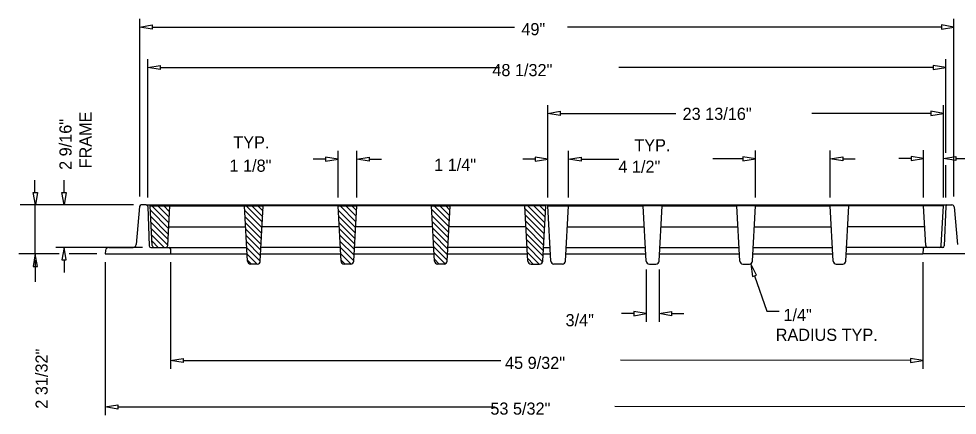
# Model space of a CAD drawing. Extents: x 12.38 to 19.62, y 5.98 to 15.83.
# Drawn here: x 12.375 to 17.009, y 10.382 to 12.339 of the extents above; entities that cross this region are included whole.
import ezdxf

# ---------------------------------------------------------------- set-up
doc = ezdxf.new("R2010")
doc.units = 0
for name, color, linetype in [('Default', 7, 'Continuous'), ('DIMS', 7, 'Continuous'), ('FRAME', 7, 'Continuous'), ('HATCH', 7, 'Continuous'), ('TOP', 7, 'Continuous'), ('V7_LEVEL_12', 7, 'Continuous')]:
    doc.layers.add(name, color=color, linetype=linetype)

# ---------------------------------------------------------------- blocks, each defined once
blk = doc.blocks.new('_X36')
at = {"layer": 'Default'}
for p, q in [((705.4, 291.74), (705.46, 291.81)), ((705.58, 288.39), (709, 291.81)), ((705.76, 285.03), (712.53, 291.81)), ((705.94, 281.68), (716.07, 291.81)), ((706.12, 278.32), (717.8, 290)), ((706.3, 274.97), (717.6, 286.26)), ((706.48, 271.61), (717.39, 282.52)), ((706.66, 268.26), (717.19, 278.79)), ((706.85, 264.9), (716.99, 275.05)), ((707.03, 261.55), (716.79, 271.31)), ((707.24, 258.23), (716.59, 267.58)), ((709.35, 256.81), (716.39, 263.84)), ((712.89, 256.81), (716.19, 260.1))]:
    blk.add_line(p, q, dxfattribs=at)
blk = doc.blocks.new('_X35')
at = {"layer": 'Default'}
for p, q in [((763.03, 289.27), (765.57, 291.81)), ((763.21, 285.92), (769.1, 291.81)), ((763.39, 282.56), (772.64, 291.81)), ((763.57, 279.21), (774.03, 289.66)), ((763.76, 275.85), (773.83, 285.92)), ((763.94, 272.5), (773.63, 282.19)), ((764.12, 269.14), (773.42, 278.45)), ((764.3, 265.79), (773.22, 274.71)), ((764.48, 262.43), (773.02, 270.98)), ((764.66, 259.08), (772.82, 267.24)), ((766.01, 256.89), (772.62, 263.5)), ((769.46, 256.81), (772.42, 259.76))]:
    blk.add_line(p, q, dxfattribs=at)
blk = doc.blocks.new('_X34')
at = {"layer": 'Default'}
for p, q in [((819.3, 288.97), (822.14, 291.81)), ((819.48, 285.61), (825.67, 291.81)), ((819.66, 282.26), (829.21, 291.81)), ((819.84, 278.9), (830.26, 289.32)), ((820.02, 275.55), (830.06, 285.59)), ((820.2, 272.19), (829.86, 281.85)), ((820.38, 268.84), (829.66, 278.11)), ((820.56, 265.49), (829.46, 274.38)), ((820.75, 262.13), (829.25, 270.64)), ((820.93, 258.78), (829.05, 266.9)), ((822.51, 256.83), (828.85, 263.17)), ((826.03, 256.81), (828.65, 259.43))]:
    blk.add_line(p, q, dxfattribs=at)
blk = doc.blocks.new('_X33')
at = {"layer": 'Default'}
for p, q in [((875.56, 288.67), (878.7, 291.81)), ((875.75, 285.31), (882.24, 291.81)), ((875.93, 281.96), (885.77, 291.81)), ((876.11, 278.6), (886.49, 288.99)), ((876.29, 275.25), (886.29, 285.25)), ((876.47, 271.89), (886.09, 281.51)), ((876.65, 268.54), (885.89, 277.78)), ((876.83, 265.18), (885.69, 274.04)), ((877.01, 261.83), (885.49, 270.3)), ((877.2, 258.48), (885.28, 266.57)), ((879.06, 256.81), (885.08, 262.83)), ((882.59, 256.81), (884.88, 259.09))]:
    blk.add_line(p, q, dxfattribs=at)
blk = doc.blocks.new('_X37')
at = {"layer": 'Default'}
for p, q in [((544.01, 208.13), (544.18, 208.3)), ((544.19, 204.78), (547.71, 208.3)), ((544.37, 201.42), (551.25, 208.3)), ((544.55, 198.07), (554.78, 208.3)), ((544.73, 194.71), (555.74, 205.72)), ((544.91, 191.36), (555.53, 201.98)), ((545.09, 188.01), (555.33, 198.24)), ((545.27, 184.65), (555.13, 194.51)), ((547.46, 183.3), (554.93, 190.77)), ((551, 183.3), (554.73, 187.03))]:
    blk.add_line(p, q, dxfattribs=at)

msp = doc.modelspace()

# ---------------------------------------------------------------- linework, layer by layer
at = {"layer": 'DIMS'}
for p, q in [((12.9725, 11.4612), (12.9725, 12.3391)), ((16.992, 11.4612), (16.992, 12.3391)), ((13.034, 12.2981), (14.8232, 12.2981)), ((16.9305, 12.2981), (15.0849, 12.2981)), ((13.0125, 11.4564), (13.0125, 12.1399)), ((16.9515, 11.6781), (16.9515, 12.1399)), ((13.074, 12.0988), (14.7493, 12.0988)), ((16.8899, 12.0988), (15.3383, 12.0988)), ((14.9873, 11.4564), (14.9873, 11.9133)), ((16.9402, 11.4564), (16.9402, 11.9133)), ((15.0488, 11.8723), (15.6199, 11.8723)), ((16.8787, 11.8723), (16.2908, 11.8723)), ((13.9516, 11.4564), (13.9516, 11.6867)), ((14.0439, 11.4564), (14.0439, 11.6867)), ((15.0896, 11.4564), (15.0896, 11.687)), ((16.0124, 11.4564), (16.0124, 11.6888)), ((16.3815, 11.4564), (16.3815, 11.6888)), ((16.8428, 11.4564), (16.8428, 11.6903)), ((13.8901, 11.6457), (13.8286, 11.6457)), ((14.1054, 11.6457), (14.1669, 11.6457)), ((14.9256, 11.646), (14.8641, 11.646)), ((15.1511, 11.646), (15.3383, 11.646)), ((15.9508, 11.6478), (15.8017, 11.6478)), ((16.443, 11.6478), (16.5045, 11.6478)), ((16.7813, 11.6493), (16.7198, 11.6493)), ((17.0017, 11.6493), (17.0632, 11.6493)), ((16.9515, 11.4564), (16.9515, 11.6165)), ((12.4552, 11.4817), (12.4552, 11.5432)), ((12.5987, 11.4817), (12.5987, 11.5432)), ((12.9411, 11.4202), (12.3824, 11.4202)), ((12.5754, 11.178), (12.3753, 11.178)), ((12.9859, 11.2103), (12.5577, 11.2103)), ((12.7613, 11.178), (12.6234, 11.178)), ((12.4563, 11.1472), (12.4563, 11.0398)), ((12.5987, 11.1488), (12.5987, 11.0873)), ((12.8023, 11.1383), (12.8023, 10.3821)), ((13.125, 11.1383), (13.125, 10.6114)), ((16.8389, 11.1383), (16.8389, 10.6114)), ((15.4734, 11.1019), (15.4734, 10.8425)), ((15.5363, 11.1019), (15.5363, 10.8425)), ((16.0075, 11.0706), (16.0685, 10.8963)), ((16.0685, 10.8963), (16.13, 10.8963)), ((15.4119, 10.8835), (15.3504, 10.8835)), ((15.5978, 10.8835), (15.6593, 10.8835)), ((13.1865, 10.6524), (14.755, 10.6524)), ((16.7774, 10.6524), (15.3465, 10.654)), ((12.8638, 10.4231), (14.7265, 10.4231)), ((17.1002, 10.4231), (15.3179, 10.4245))]:
    msp.add_line(p, q, dxfattribs=at)
for points in [[(13.034, 12.3084), (13.034, 12.2879), (12.9725, 12.2981)], [(16.9305, 12.3084), (16.9305, 12.2879), (16.992, 12.2981)], [(13.074, 12.1091), (13.074, 12.0886), (13.0125, 12.0988)], [(16.8899, 12.1091), (16.8899, 12.0886), (16.9515, 12.0988)], [(15.0488, 11.8825), (15.0488, 11.862), (14.9873, 11.8723)], [(16.8787, 11.8825), (16.8787, 11.862), (16.9402, 11.8723)], [(13.8901, 11.6559), (13.8901, 11.6354), (13.9516, 11.6457)], [(14.1054, 11.6559), (14.1054, 11.6354), (14.0439, 11.6457)], [(14.9256, 11.6562), (14.9256, 11.6357), (14.9871, 11.646)], [(15.1511, 11.6562), (15.1511, 11.6357), (15.0896, 11.646)], [(15.9508, 11.6581), (15.9508, 11.6376), (16.0124, 11.6478)], [(16.443, 11.6581), (16.443, 11.6376), (16.3815, 11.6478)], [(16.7813, 11.6596), (16.7813, 11.6391), (16.8428, 11.6493)], [(17.0017, 11.6596), (17.0017, 11.6391), (16.9402, 11.6493)], [(12.4469, 11.4817), (12.4674, 11.4817), (12.4572, 11.4202)], [(12.5885, 11.4817), (12.609, 11.4817), (12.5987, 11.4202)], [(12.4467, 11.1165), (12.4672, 11.1165), (12.457, 11.178)], [(12.5885, 11.1488), (12.609, 11.1488), (12.5987, 11.2103)], [(15.9977, 11.0676), (16.0173, 11.0736), (15.9893, 11.1294)], [(15.4119, 10.8938), (15.4119, 10.8733), (15.4734, 10.8835)], [(15.5978, 10.8938), (15.5978, 10.8733), (15.5363, 10.8835)], [(13.1865, 10.6627), (13.1865, 10.6422), (13.125, 10.6524)], [(16.7774, 10.6627), (16.7774, 10.6422), (16.8389, 10.6524)], [(12.8638, 10.4333), (12.8638, 10.4128), (12.8023, 10.4231)]]:
    msp.add_lwpolyline(points, close=True, dxfattribs=at)
at = {"layer": 'FRAME'}
for p, q in [((12.9718, 11.4132), (12.9553, 11.2244)), ((13.0047, 11.4202), (12.9795, 11.4202)), ((13.0047, 11.4202), (16.9579, 11.4202)), ((13.0124, 11.4128), (13.0192, 11.2177)), ((16.9515, 11.4128), (16.9447, 11.2177)), ((16.9592, 11.4202), (16.9826, 11.4202)), ((16.9928, 11.4109), (17.0091, 11.2244)), ((12.8032, 11.195), (12.8023, 11.178)), ((12.8023, 11.178), (13.125, 11.178)), ((12.8193, 11.2103), (12.94, 11.2103)), ((13.0269, 11.2103), (13.1172, 11.2103)), ((13.1236, 11.2042), (13.125, 11.178)), ((13.125, 11.178), (13.503, 11.178)), ((13.5697, 11.178), (13.9644, 11.178)), ((14.0311, 11.178), (14.4258, 11.178)), ((14.4924, 11.178), (14.8871, 11.178)), ((14.964, 11.178), (14.9999, 11.178)), ((14.9658, 11.2103), (14.9982, 11.2103)), ((15.0768, 11.178), (15.4715, 11.178)), ((15.5382, 11.178), (15.9329, 11.178)), ((15.9996, 11.178), (16.3943, 11.178)), ((16.4609, 11.178), (16.8389, 11.178)), ((16.8403, 11.2042), (16.8389, 11.178)), ((17.1617, 11.178), (16.8389, 11.178)), ((16.937, 11.2103), (16.8468, 11.2103))]:
    msp.add_line(p, q, dxfattribs=at)
for centre, radius, start, end in [((12.9795, 11.4125), 0.00769, 90, 175), ((13.0047, 11.4125), 0.00769, 2, 90), ((16.9592, 11.4125), 0.00769, 90, 178), ((16.9826, 11.41), 0.0103, 5, 90), ((12.94, 11.2257), 0.0154, 270, 355), ((13.0269, 11.218), 0.00769, 182, 270), ((16.937, 11.218), 0.00769, 270, 358), ((12.8193, 11.1942), 0.0161, 90, 177), ((13.1172, 11.2038), 0.00648, 3, 90), ((16.8468, 11.2038), 0.00648, 90, 177)]:
    msp.add_arc(centre, radius, start, end, dxfattribs=at)
at = {"layer": 'TOP'}
for p, q in [((13.0343, 11.22), (13.0237, 11.4154)), ((13.0237, 11.4154), (13.1211, 11.4154)), ((13.1106, 11.22), (13.1211, 11.4154)), ((13.1211, 11.4154), (13.4902, 11.4154)), ((13.5049, 11.143), (13.4902, 11.4154)), ((13.4902, 11.4154), (13.5825, 11.4154)), ((13.5678, 11.143), (13.5825, 11.4154)), ((13.9516, 11.4154), (13.5825, 11.4154)), ((13.9663, 11.143), (13.9516, 11.4154)), ((13.9516, 11.4154), (14.0439, 11.4154)), ((14.0292, 11.143), (14.0439, 11.4154)), ((14.413, 11.4154), (14.0439, 11.4154)), ((14.413, 11.4154), (14.5052, 11.4154)), ((14.4276, 11.143), (14.413, 11.4154)), ((14.4905, 11.143), (14.5052, 11.4154)), ((14.8743, 11.4154), (14.5052, 11.4154)), ((14.9768, 11.4154), (14.8743, 11.4154)), ((14.889, 11.1429), (14.8743, 11.4154)), ((14.9621, 11.1429), (14.9768, 11.4154)), ((14.9871, 11.4154), (15.0896, 11.4154)), ((15.0018, 11.1429), (14.9871, 11.4154)), ((15.0749, 11.1429), (15.0896, 11.4154)), ((15.0896, 11.4154), (15.4587, 11.4154)), ((15.4734, 11.143), (15.4587, 11.4154)), ((15.551, 11.4154), (15.4587, 11.4154)), ((15.5363, 11.143), (15.551, 11.4154)), ((15.551, 11.4154), (15.9201, 11.4154)), ((15.9348, 11.143), (15.9201, 11.4154)), ((16.0124, 11.4154), (15.9201, 11.4154)), ((15.9977, 11.143), (16.0124, 11.4154)), ((16.0124, 11.4154), (16.3815, 11.4154)), ((16.3961, 11.143), (16.3815, 11.4154)), ((16.4737, 11.4154), (16.3815, 11.4154)), ((16.459, 11.143), (16.4737, 11.4154)), ((16.8428, 11.4154), (16.4737, 11.4154)), ((16.9402, 11.4154), (16.8428, 11.4154)), ((16.8534, 11.22), (16.8428, 11.4154)), ((16.9297, 11.22), (16.9402, 11.4154)), ((13.1156, 11.3128), (13.495, 11.3128)), ((13.9564, 11.3128), (13.5777, 11.3128)), ((14.4178, 11.3128), (14.0391, 11.3128)), ((14.8798, 11.3128), (14.5004, 11.3128)), ((15.0841, 11.3128), (15.4635, 11.3128)), ((15.5462, 11.3128), (15.9249, 11.3128)), ((16.0076, 11.3128), (16.3863, 11.3128)), ((16.8483, 11.3128), (16.4689, 11.3128)), ((13.0445, 11.2103), (13.1003, 11.2103)), ((13.1003, 11.2103), (13.5013, 11.2103)), ((13.9626, 11.2103), (13.5714, 11.2103)), ((14.424, 11.2103), (14.0328, 11.2103)), ((14.8854, 11.2103), (14.4942, 11.2103)), ((15.0786, 11.2103), (15.4698, 11.2103)), ((15.5399, 11.2103), (15.9311, 11.2103)), ((16.0013, 11.2103), (16.3925, 11.2103)), ((16.8636, 11.2103), (16.4627, 11.2103)), ((16.9194, 11.2103), (16.8636, 11.2103)), ((13.5524, 11.1283), (13.5203, 11.1283)), ((14.0138, 11.1283), (13.9816, 11.1283)), ((14.4752, 11.1283), (14.443, 11.1283)), ((14.9044, 11.1283), (14.9468, 11.1283)), ((15.0596, 11.1283), (15.0172, 11.1283)), ((15.4888, 11.1283), (15.5209, 11.1283)), ((15.9501, 11.1283), (15.9823, 11.1283)), ((16.4115, 11.1283), (16.4437, 11.1283))]:
    msp.add_line(p, q, dxfattribs=at)
for centre, radius, start, end in [((13.0445, 11.2206), 0.0103, 183.0871, 270), ((13.1003, 11.2206), 0.0103, 270, 356.9129), ((16.8636, 11.2206), 0.0103, 183.0871, 270), ((16.9194, 11.2206), 0.0103, 270, 356.9129), ((13.5203, 11.1437), 0.0154, 182.6838, 270), ((13.5524, 11.1437), 0.0154, 270, 357.3162), ((13.9816, 11.1437), 0.0154, 182.6838, 270), ((14.0138, 11.1437), 0.0154, 270, 357.3162), ((14.443, 11.1437), 0.0154, 182.6838, 270), ((14.4752, 11.1437), 0.0154, 270, 357.3162), ((14.9044, 11.1437), 0.0154, 183.0871, 270), ((14.9468, 11.1437), 0.0154, 270, 356.9129), ((15.0172, 11.1437), 0.0154, 183.0871, 270), ((15.0596, 11.1437), 0.0154, 270, 356.9129), ((15.4888, 11.1437), 0.0154, 182.6838, 270), ((15.5209, 11.1437), 0.0154, 270, 357.3162), ((15.9501, 11.1437), 0.0154, 182.6838, 270), ((15.9823, 11.1437), 0.0154, 270, 357.3162), ((16.4115, 11.1437), 0.0154, 182.6838, 270), ((16.4437, 11.1437), 0.0154, 270, 357.3162)]:
    msp.add_arc(centre, radius, start, end, dxfattribs=at)
at = {"layer": 'V7_LEVEL_12'}
msp.add_line((12.457, 11.178), (12.457, 11.4209), dxfattribs=at)

# ---------------------------------------------------------------- block references
at = {"layer": 'HATCH', "xscale": 0.008202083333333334, "yscale": -0.008202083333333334, "rotation": 180}
for name, p in [('_X37', (17.5831, 9.7069)), ('_X33', (20.7626, 9.022)), ('_X34', (20.7626, 9.022)), ('_X35', (20.7626, 9.022)), ('_X36', (20.7626, 9.022))]:
    msp.add_blockref(name, p, dxfattribs=at)

# ---------------------------------------------------------------- texts
at = {"layer": 'V7_LEVEL_12'}
for s, p in [('49"', (14.8567, 12.2578)), (' 48 1/32"', (14.6911, 12.0558)), ('23 13/16"', (15.6527, 11.8399)), ('TYP.', (13.4344, 11.6991)), ('TYP.', (15.4143, 11.6847)), ('1 1/8"', (13.4156, 11.584)), ('1 1/4"', (14.426, 11.5882)), ('4 1/2"', (15.3356, 11.5788)), ('1/4"', (16.1508, 10.8471)), ('3/4"', (15.0748, 10.8213)), ('RADIUS TYP.', (16.1124, 10.7492)), ('45 9/32"', (14.7761, 10.6106)), (' 53 5/32"', (14.6813, 10.3848))]:
    msp.add_text(s, height=0.06, dxfattribs=at).set_placement(p)
for s, p in [('FRAME', (12.7348, 11.6004)), ('2 9/16"', (12.636, 11.593)), (' 2 31/32"', (12.518, 10.3919))]:
    msp.add_text(s, height=0.06, rotation=90, dxfattribs=at).set_placement(p)

doc.saveas('drawing.dxf')
